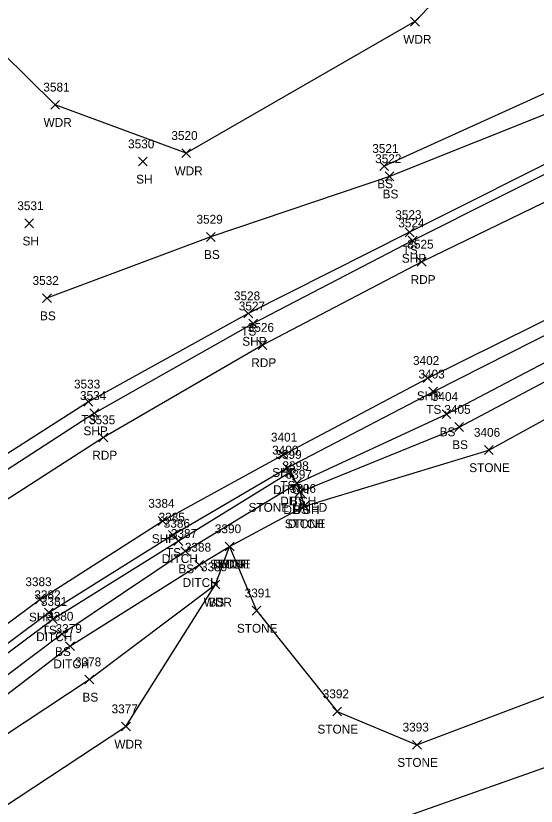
# Model space of a CAD drawing. Extents: x 1623612 to 1625808, y 621345 to 627748.
# Drawn here: x 1625111.7 to 1625229.6, y 626826.7 to 627005.8 of the extents above; entities that cross this region are included whole.
import ezdxf

# ---------------------------------------------------------------- set-up
doc = ezdxf.new("R2010")
doc.units = 0
for name, color, linetype in [('D_A', 7, 'Continuous'), ('D_C', 7, 'Continuous'), ('D_I', 7, 'Continuous'), ('D_TIC', 7, 'Continuous'), ('DD', 7, 'Continuous'), ('L_A', 7, 'Continuous'), ('L_I', 7, 'Continuous'), ('L_TIC', 7, 'Continuous'), ('LASF', 7, 'Continuous'), ('LAWA', 7, 'Continuous'), ('LELB', 7, 'Continuous'), ('LSOGP', 7, 'Continuous'), ('P_A', 7, 'Continuous'), ('P_I', 7, 'Continuous'), ('P_TIC', 7, 'Continuous'), ('PET', 7, 'Continuous'), ('PSP', 7, 'Continuous')]:
    doc.layers.add(name, color=color, linetype=linetype)

msp = doc.modelspace()

# ---------------------------------------------------------------- linework, layer by layer
at = {"layer": 'D_TIC'}
for points in [[(1625172.75, 626901.4), (1625174.75, 626903.4)], [(1625174.75, 626901.4), (1625172.75, 626903.4)], [(1625172.75, 626901.4), (1625174.75, 626903.4)], [(1625174.75, 626901.4), (1625172.75, 626903.4)], [(1625174.36, 626898.84), (1625176.36, 626900.84)], [(1625176.36, 626898.84), (1625174.36, 626900.84)], [(1625175.09, 626896.9), (1625177.09, 626898.9)], [(1625177.09, 626896.9), (1625175.09, 626898.9)], [(1625176.06, 626893.7), (1625178.06, 626895.7)], [(1625178.06, 626893.7), (1625176.06, 626895.7)], [(1625147.51, 626885.8), (1625149.51, 626887.8)], [(1625149.51, 626885.8), (1625147.51, 626887.8)], [(1625159.13, 626884.56), (1625161.13, 626886.56)], [(1625161.13, 626884.56), (1625159.13, 626886.56)], [(1625152.24, 626880.37), (1625154.24, 626882.37)], [(1625154.24, 626880.37), (1625152.24, 626882.37)], [(1625119.07, 626868.1), (1625121.07, 626870.1)], [(1625121.07, 626868.1), (1625119.07, 626870.1)], [(1625122.95, 626861.95), (1625124.95, 626863.95)], [(1625124.95, 626861.95), (1625122.95, 626863.95)]]:
    msp.add_lwpolyline(points, dxfattribs=at)
at = {"layer": 'DD'}
for points in [[(1625081.1, 626839.99), (1625120.07, 626869.1), (1625148.51, 626886.8), (1625173.75, 626902.4)], [(1625081.1, 626839.99), (1625083.54, 626836.73), (1625085.53, 626833.57), (1625123.95, 626862.95), (1625153.24, 626881.37), (1625160.13, 626885.56), (1625177.06, 626894.7), (1625176.09, 626897.9), (1625175.36, 626899.84), (1625173.75, 626902.4)]]:
    msp.add_lwpolyline(points, dxfattribs=at)
at = {"layer": 'L_TIC'}
for points in [[(1625201.12, 627003.43), (1625203.12, 627005.43)], [(1625203.12, 627003.43), (1625201.12, 627005.43)], [(1625119.61, 626984.6), (1625121.61, 626986.6)], [(1625121.61, 626984.6), (1625119.61, 626986.6)], [(1625149.28, 626973.64), (1625151.28, 626975.64)], [(1625151.28, 626973.64), (1625149.28, 626975.64)], [(1625139.47, 626971.74), (1625141.47, 626973.74)], [(1625141.47, 626971.74), (1625139.47, 626973.74)], [(1625194.14, 626970.7), (1625196.14, 626972.7)], [(1625196.14, 626970.7), (1625194.14, 626972.7)], [(1625195.36, 626968.39), (1625197.36, 626970.39)], [(1625197.36, 626968.39), (1625195.36, 626970.39)], [(1625113.71, 626957.74), (1625115.71, 626959.74)], [(1625115.71, 626957.74), (1625113.71, 626959.74)], [(1625199.92, 626955.72), (1625201.92, 626957.72)], [(1625201.92, 626955.72), (1625199.92, 626957.72)], [(1625154.89, 626954.67), (1625156.89, 626956.67)], [(1625156.89, 626954.67), (1625154.89, 626956.67)], [(1625117.73, 626940.79), (1625119.73, 626942.79)], [(1625119.73, 626940.79), (1625117.73, 626942.79)], [(1625163.36, 626937.31), (1625165.36, 626939.31)], [(1625165.36, 626937.31), (1625163.36, 626939.31)], [(1625205.27, 626919.6), (1625207.27, 626921.6)], [(1625207.27, 626919.6), (1625205.27, 626921.6)], [(1625127.12, 626917.34), (1625129.12, 626919.34)], [(1625129.12, 626917.34), (1625127.12, 626919.34)], [(1625208.28, 626914.51), (1625210.28, 626916.51)], [(1625210.28, 626914.51), (1625208.28, 626916.51)], [(1625211.13, 626911.6), (1625213.13, 626913.6)], [(1625213.13, 626911.6), (1625211.13, 626913.6)], [(1625217.88, 626906.4), (1625219.88, 626908.4)], [(1625219.88, 626906.4), (1625217.88, 626908.4)], [(1625172.2, 626902.38), (1625174.2, 626904.38)], [(1625174.2, 626902.38), (1625172.2, 626904.38)], [(1625174.36, 626898.84), (1625176.36, 626900.84)], [(1625176.36, 626898.84), (1625174.36, 626900.84)], [(1625175.09, 626896.9), (1625177.09, 626898.9)], [(1625177.09, 626896.9), (1625175.09, 626898.9)], [(1625176.06, 626893.7), (1625178.06, 626895.7)], [(1625178.06, 626893.7), (1625176.06, 626895.7)], [(1625146.29, 626887.18), (1625148.29, 626889.18)], [(1625148.29, 626887.18), (1625146.29, 626889.18)], [(1625159.13, 626884.56), (1625161.13, 626886.56)], [(1625161.13, 626884.56), (1625159.13, 626886.56)], [(1625159.13, 626884.56), (1625161.13, 626886.56)], [(1625161.13, 626884.56), (1625159.13, 626886.56)], [(1625149.08, 626883.49), (1625151.08, 626885.49)], [(1625151.08, 626883.49), (1625149.08, 626885.49)], [(1625155.9, 626875.93), (1625157.9, 626877.93)], [(1625157.9, 626875.93), (1625155.9, 626877.93)], [(1625155.9, 626875.93), (1625157.9, 626877.93)], [(1625157.9, 626875.93), (1625155.9, 626877.93)], [(1625118.15, 626869.61), (1625120.15, 626871.61)], [(1625120.15, 626869.61), (1625118.15, 626871.61)], [(1625165.23, 626870.01), (1625167.23, 626872.01)], [(1625167.23, 626870.01), (1625165.23, 626872.01)], [(1625121.13, 626864.73), (1625123.13, 626866.73)], [(1625123.13, 626864.73), (1625121.13, 626866.73)], [(1625127.34, 626854.41), (1625129.34, 626856.41)], [(1625129.34, 626854.41), (1625127.34, 626856.41)], [(1625183.49, 626847.17), (1625185.49, 626849.17)], [(1625185.49, 626847.17), (1625183.49, 626849.17)], [(1625135.64, 626843.76), (1625137.64, 626845.76)], [(1625137.64, 626843.76), (1625135.64, 626845.76)], [(1625201.58, 626839.63), (1625203.58, 626841.63)], [(1625203.58, 626839.63), (1625201.58, 626841.63)]]:
    msp.add_lwpolyline(points, dxfattribs=at)
at = {"layer": 'LASF'}
for points in [[(1625177.06, 626894.7), (1625218.88, 626907.4), (1625254.03, 626926.66), (1625306.85, 626949.98), (1625346.65, 626969.47), (1625384.02, 626990.2), (1625407.28, 626970.97)], [(1625160.13, 626885.56), (1625166.23, 626871.01), (1625184.49, 626848.17), (1625202.58, 626840.63), (1625237.88, 626854), (1625291.03, 626879.76), (1625353.61, 626907.53), (1625390.22, 626926.27), (1625415.04, 626948.64), (1625407.28, 626970.97)]]:
    msp.add_lwpolyline(points, dxfattribs=at)
at = {"layer": 'LAWA'}
for points in [[(1625415.15, 627106.89), (1625382.7, 627098.88), (1625336.27, 627080.42), (1625320.48, 627063.82), (1625320.52, 627063.67), (1625304.7, 627054.6), (1625267.78, 627034.56), (1625224.16, 627026.96), (1625202.12, 627004.43), (1625150.28, 626974.64), (1625120.61, 626985.6), (1625102.29, 627003.55), (1625124.36, 627037.24), (1625145.75, 627068.46), (1625178.32, 627095.73), (1625213.7, 627126.41), (1625246.32, 627163.64), (1625275.84, 627203.6), (1625300.5, 627239.13), (1625315, 627239.75)], [(1625011.66, 626754.51), (1625041.42, 626781.36), (1625076.28, 626803.36), (1625105.24, 626824.17), (1625136.64, 626844.76), (1625156.9, 626876.93), (1625160.13, 626885.56)]]:
    msp.add_lwpolyline(points, dxfattribs=at)
at = {"layer": 'LELB'}
for points in [[(1625469.29, 627095.38), (1625429.94, 627072.01), (1625396.47, 627056.33), (1625363.17, 627036.91), (1625324.86, 627017.28), (1625282.83, 626996.93), (1625240.1, 626976.36), (1625200.92, 626956.72), (1625164.36, 626938.31), (1625128.12, 626918.34), (1625094.57, 626896.89), (1625066.91, 626876.48), (1625035.19, 626854.3), (1625018.18, 626859.5), (1625006.28, 626868.94), (1625007.56, 626879.04), (1625022.39, 626921.76), (1625036.67, 626956.96), (1625050.15, 626986.83), (1625070.28, 627027.73), (1625085.48, 627058.74), (1625111, 627101.13), (1625130.83, 627129.7)], [(1625459.45, 627108.93), (1625422.64, 627088.23), (1625389.38, 627068.23), (1625357.1, 627050.98), (1625318.54, 627029.39), (1625278.3, 627010.79), (1625234, 626989.32), (1625195.14, 626971.7)], [(1625466.12, 627099.72), (1625426.45, 627080.76), (1625391.19, 627065.04), (1625359.75, 627046.45), (1625320.22, 627026.23), (1625279.53, 627006.16), (1625236.1, 626985.25), (1625196.36, 626969.39), (1625155.89, 626955.67), (1625118.73, 626941.79)], [(1625083.53, 626780.74), (1625137.04, 626804.12), (1625178.43, 626816.77), (1625245.42, 626840.4), (1625308.04, 626871.64), (1625357.38, 626894.72), (1625395.36, 626919.42), (1625409.95, 626928.75), (1625453.5, 626946.29), (1625490.76, 626971.58), (1625536.74, 626991.35)], [(1625176.09, 626897.9), (1625212.13, 626912.6), (1625250, 626932.63), (1625300.49, 626956.39), (1625342.51, 626976.49), (1625371.92, 626991.22)], [(1624803, 626375.22), (1624813.35, 626398.45), (1624825.59, 626427.7), (1624842.6, 626469.77), (1624853.82, 626508.25), (1624866.96, 626541.11), (1624879.6, 626570.92), (1624891.67, 626600.55), (1624909.69, 626627.37), (1624926.15, 626668.66), (1624945.08, 626696.18), (1624959.4, 626716.07), (1624979.06, 626741.61), (1624996.92, 626763.33), (1625023.93, 626790.77), (1625051.04, 626817.18), (1625076.24, 626838.55), (1625119.15, 626870.61), (1625147.29, 626888.18), (1625173.2, 626903.38), (1625206.27, 626920.6), (1625246.39, 626940.92)], [(1624810.6, 626380.38), (1624818.04, 626393.96), (1624831.09, 626425.55), (1624850.8, 626470.91), (1624859.76, 626506.71), (1624871.37, 626535.84), (1624886.95, 626567.84), (1624894.07, 626585.15), (1624895.49, 626590.47), (1624915.6, 626622.48), (1624934.63, 626664.39), (1624951.07, 626691.63), (1624965.13, 626713.06), (1624983.66, 626737.48), (1625004.4, 626758.94), (1625029.36, 626786.77), (1625054.16, 626807.16), (1625052.62, 626815.07), (1625083.54, 626836.73), (1625122.13, 626865.73), (1625150.08, 626884.49), (1625175.36, 626899.84), (1625209.28, 626915.51), (1625248.24, 626935.95)], [(1624815.3, 626378.44), (1624822.97, 626393.02), (1624835.07, 626424.21), (1624854.93, 626470.78), (1624864.02, 626503.22), (1624876, 626534.5), (1624889.39, 626566.85), (1624897.36, 626584.29), (1624900.1, 626587.8), (1624917.68, 626620.81), (1624936.92, 626663.47), (1624953.32, 626690.33), (1624968.57, 626711.23), (1624977.21, 626720.96), (1624986.38, 626735.04), (1625009.06, 626756.63), (1625033.16, 626784.59), (1625055.85, 626805.24), (1625057.84, 626806.47), (1625088.69, 626829.26), (1625128.34, 626855.41), (1625156.9, 626876.93)]]:
    msp.add_lwpolyline(points, dxfattribs=at)
at = {"layer": 'LSOGP'}
for points in [[(1625267.78, 627034.56), (1625224.16, 627026.96), (1625202.12, 627004.43), (1625150.28, 626974.64), (1625120.61, 626985.6), (1625102.29, 627003.55), (1625124.36, 627037.24), (1625145.75, 627068.46), (1625178.32, 627095.73), (1625213.7, 627126.41)], [(1625003.85, 626671.41), (1625025.16, 626699.11), (1625051.25, 626730.7), (1625074.8, 626766.7), (1625081.53, 626774.17), (1625137.04, 626804.12), (1625178.43, 626816.77), (1625245.42, 626840.4)]]:
    msp.add_lwpolyline(points, dxfattribs=at)
at = {"layer": 'P_TIC'}
for points in [[(1625200.61, 626953.83), (1625202.61, 626955.83)], [(1625202.61, 626953.83), (1625200.61, 626955.83)], [(1625202.66, 626949.01), (1625204.66, 626951.01)], [(1625204.66, 626949.01), (1625202.66, 626951.01)], [(1625164.46, 626935.02), (1625166.46, 626937.02)], [(1625166.46, 626935.02), (1625164.46, 626937.02)], [(1625166.56, 626930.17), (1625168.56, 626932.17)], [(1625168.56, 626930.17), (1625166.56, 626932.17)], [(1625204.02, 626922.68), (1625206.02, 626924.68)], [(1625206.02, 626922.68), (1625204.02, 626924.68)], [(1625128.49, 626914.73), (1625130.49, 626916.73)], [(1625130.49, 626914.73), (1625128.49, 626916.73)], [(1625130.52, 626909.23), (1625132.52, 626911.23)], [(1625132.52, 626909.23), (1625130.52, 626911.23)], [(1625171.26, 626905.31), (1625173.26, 626907.31)], [(1625173.26, 626905.31), (1625171.26, 626907.31)], [(1625143.96, 626890.32), (1625145.96, 626892.32)], [(1625145.96, 626890.32), (1625143.96, 626892.32)], [(1625116.11, 626872.56), (1625118.11, 626874.56)], [(1625118.11, 626872.56), (1625116.11, 626874.56)]]:
    msp.add_lwpolyline(points, dxfattribs=at)
at = {"layer": 'PET'}
msp.add_lwpolyline([(1625473.25, 627090.09), (1625432.8, 627065.24), (1625401.59, 627047.56), (1625365.67, 627029.01), (1625328.14, 627010.31), (1625285.33, 626989.61), (1625243.69, 626969.41), (1625203.66, 626950.01), (1625167.56, 626931.17), (1625131.52, 626910.23), (1625100.02, 626889.97), (1625071.13, 626869.72), (1625042.82, 626845.85)], dxfattribs=at)
at = {"layer": 'PSP'}
for points in [[(1625241.24, 626974.73), (1625201.61, 626954.83), (1625165.46, 626936.02), (1625129.49, 626915.73), (1625096.75, 626894.53), (1625068.02, 626874.53), (1625037.74, 626850.73), (1625034.4, 626848.36), (1625028.88, 626848.44), (1625014.47, 626855.76), (1625006.34, 626861.28), (1625002.17, 626866.44), (1625001.48, 626875.79), (1625020.05, 626923.14), (1625034.42, 626958.47), (1625047.14, 626987.9), (1625066.83, 627030.1), (1625082.81, 627060.49), (1625108.38, 627102.81), (1625128.19, 627131.96)], [(1624794.65, 626368.04), (1624800.63, 626383.44), (1624817.3, 626423.08), (1624832.73, 626462.11), (1624850.47, 626510.04), (1624865.43, 626546.52), (1624882.91, 626590.11), (1624893.72, 626613.2), (1624905.71, 626637.22), (1624924.51, 626670), (1624942.43, 626698.12), (1624956.64, 626717.85), (1624976.67, 626743.84), (1624995.18, 626765.37), (1625020.7, 626793.24), (1625048.65, 626820.06), (1625074.48, 626841.9), (1625117.11, 626873.56), (1625144.96, 626891.32), (1625172.26, 626906.31), (1625205.02, 626923.68), (1625245.42, 626943.67)]]:
    msp.add_lwpolyline(points, dxfattribs=at)

# ---------------------------------------------------------------- texts
at = {"layer": 'D_A'}
for p in [(1625169.99, 626897.4), (1625169.99, 626897.4), (1625171.59, 626894.84), (1625172.32, 626892.9), (1625173.3, 626889.7), (1625144.75, 626881.8), (1625156.37, 626880.56), (1625149.48, 626876.37), (1625116.3, 626864.1), (1625120.19, 626857.95)]:
    msp.add_text('DITCH', height=2, dxfattribs=at).set_placement(p)
at = {"layer": 'D_C'}
msp.add_text('STONE LINED', height=2, dxfattribs=at).set_placement((1625164.42, 626893.4))
msp.add_text('STONE LINED', height=2, dxfattribs=at).set_placement((1625164.42, 626893.4))
at = {"layer": 'D_I'}
for s, p in [('3399', (1625170.49, 626905.4)), ('3399', (1625170.49, 626905.4)), ('3398', (1625172.1, 626902.84)), ('3397', (1625172.83, 626900.9)), ('3396', (1625173.75, 626897.7)), ('3386', (1625145.2, 626889.8)), ('3390', (1625156.79, 626888.56)), ('3388', (1625149.98, 626884.37)), ('3381', (1625117.37, 626872.1)), ('3379', (1625120.69, 626865.95))]:
    msp.add_text(s, height=2, dxfattribs=at).set_placement(p)
at = {"layer": 'L_A'}
for s, p in [('WDR', (1625199.48, 626999.43)), ('WDR', (1625117.97, 626980.6)), ('WDR', (1625147.64, 626969.64)), ('SH', (1625138.96, 626967.74)), ('BS', (1625193.58, 626966.7)), ('BS', (1625194.8, 626964.39)), ('SH', (1625113.2, 626953.74)), ('TS', (1625199.33, 626951.72)), ('BS', (1625154.33, 626950.67)), ('BS', (1625117.17, 626936.79)), ('TS', (1625162.77, 626933.31)), ('TS', (1625204.68, 626915.6)), ('TS', (1625126.53, 626913.34)), ('BS', (1625207.73, 626910.51)), ('BS', (1625210.57, 626907.6)), ('STONE', (1625214.42, 626902.4)), ('TS', (1625171.61, 626898.38)), ('BS', (1625173.8, 626894.84)), ('BS', (1625174.53, 626892.9)), ('STONE', (1625172.61, 626889.7)), ('TS', (1625145.7, 626883.18)), ('STONE', (1625155.68, 626880.56)), ('WDR', (1625157.49, 626880.56)), ('BS', (1625148.52, 626879.49)), ('WDR', (1625154.27, 626871.93)), ('BS', (1625155.35, 626871.93)), ('TS', (1625117.56, 626865.61)), ('STONE', (1625161.77, 626866.01)), ('BS', (1625120.57, 626860.73)), ('BS', (1625126.78, 626850.41)), ('STONE', (1625180.03, 626843.17)), ('WDR', (1625134.01, 626839.76)), ('STONE', (1625198.12, 626835.63))]:
    msp.add_text(s, height=2, dxfattribs=at).set_placement(p)
at = {"layer": 'L_I'}
for s, p in [('3581', (1625117.92, 626988.6)), ('3520', (1625146.93, 626977.64)), ('3530', (1625137.12, 626975.74)), ('3521', (1625192.45, 626974.7)), ('3522', (1625193.1, 626972.39)), ('3531', (1625112.02, 626961.74)), ('3529', (1625152.62, 626958.67)), ('3523', (1625197.66, 626959.72)), ('3532', (1625115.47, 626944.79)), ('3528', (1625161.1, 626941.31)), ('3403', (1625202.93, 626923.6)), ('3533', (1625124.86, 626921.34)), ('3404', (1625205.95, 626918.51)), ('3405', (1625208.79, 626915.6)), ('3406', (1625215.48, 626910.4)), ('3400', (1625169.77, 626906.38)), ('3398', (1625172.1, 626902.84)), ('3397', (1625172.83, 626900.9)), ('3396', (1625173.75, 626897.7)), ('3385', (1625144.03, 626891.18)), ('3387', (1625146.82, 626887.49)), ('3390', (1625156.79, 626888.56)), ('3390', (1625156.79, 626888.56)), ('3389', (1625153.64, 626879.93)), ('3389', (1625153.64, 626879.93)), ('3382', (1625115.89, 626873.61)), ('3391', (1625163.53, 626874.01)), ('3380', (1625118.78, 626868.73)), ('3378', (1625125.08, 626858.41)), ('3392', (1625181.23, 626851.17)), ('3377', (1625133.38, 626847.76)), ('3393', (1625199.32, 626843.63))]:
    msp.add_text(s, height=2, dxfattribs=at).set_placement(p)
at = {"layer": 'P_A'}
for s, p in [('SHP', (1625199.15, 626949.83)), ('RDP', (1625201.15, 626945.01)), ('SHP', (1625162.99, 626931.02)), ('RDP', (1625165.04, 626926.17)), ('SHP', (1625202.55, 626918.68)), ('SHP', (1625127.02, 626910.73)), ('RDP', (1625129.01, 626905.23)), ('SHP', (1625169.79, 626901.31)), ('SHP', (1625142.49, 626886.32)), ('SHP', (1625114.65, 626868.56))]:
    msp.add_text(s, height=2, dxfattribs=at).set_placement(p)
at = {"layer": 'P_I'}
for s, p in [('3524', (1625198.35, 626957.83)), ('3525', (1625200.4, 626953.01)), ('3527', (1625162.2, 626939.02)), ('3526', (1625164.24, 626934.17)), ('3402', (1625201.68, 626926.68)), ('3534', (1625126.23, 626918.73)), ('3535', (1625128.26, 626913.23)), ('3401', (1625169.49, 626909.31)), ('3384', (1625141.7, 626894.32)), ('3383', (1625113.85, 626876.56))]:
    msp.add_text(s, height=2, dxfattribs=at).set_placement(p)

doc.saveas('drawing.dxf')
